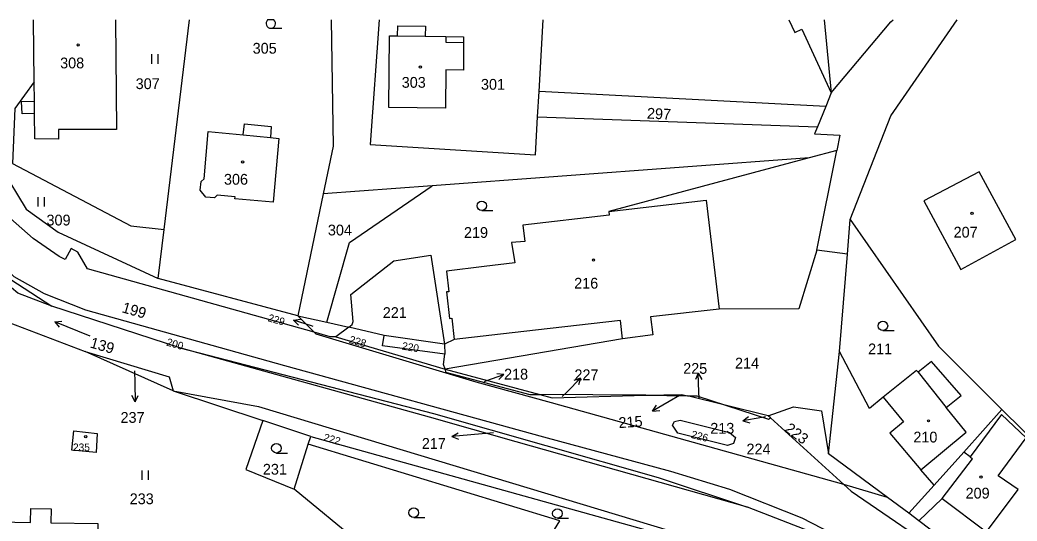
# Model space of a CAD drawing. Extents: x -520431 to -517205, y -1075927 to -1074013.
# Drawn here: x -518035.5 to -517878.1, y -1074093.8 to -1074014.8 of the extents above; entities that cross this region are included whole.
import ezdxf

# ---------------------------------------------------------------- set-up
doc = ezdxf.new("R2010")
doc.units = 0
for name, color, linetype in [('Hranice parcel', 7, 'Continuous'), ('Parcelní čísla', 7, 'Continuous'), ('Pop  PČ popisy', 7, 'Continuous'), ('Vnitřní kresba', 7, 'Continuous'), ('Značky budov', 7, 'Continuous'), ('Značky kultur', 7, 'Continuous')]:
    doc.layers.add(name, color=color, linetype=linetype)

msp = doc.modelspace()

# ---------------------------------------------------------------- linework, layer by layer
at = {"layer": 'Hranice parcel'}
for p, q in [((-518033.22, -1074024.56), (-518033.34, -1074014.78)), ((-518012.72, -1074047.85), (-518008.75, -1074014.78)), ((-517986.35, -1074014.78), (-517986.05, -1074034.68)), ((-518033.18, -1074027.62), (-518033.22, -1074024.56)), ((-517953.81, -1074030.04), (-517953.57, -1074026.08)), ((-517908.34, -1074028.41), (-517953.57, -1074026.08)), ((-517907.48, -1074026.26), (-517908.34, -1074028.41)), ((-517908.34, -1074028.41), (-517909.63, -1074031.62)), ((-517953.81, -1074030.04), (-517909.63, -1074031.62)), ((-517986.05, -1074034.68), (-517987.62, -1074042.23)), ((-517906.59, -1074035.35), (-517910.97, -1074036.55)), ((-517909.74, -1074051.08), (-517906.59, -1074035.35)), ((-517910.97, -1074036.55), (-517970.43, -1074040.96)), ((-517910.97, -1074036.55), (-517942.57, -1074044.98)), ((-517970.43, -1074040.96), (-517987.62, -1074042.23)), ((-517987.62, -1074042.23), (-517991.61, -1074061.46)), ((-517904.92, -1074051.73), (-517904.47, -1074046.28)), ((-518013.65, -1074055.54), (-518012.72, -1074047.85)), ((-517904.92, -1074051.73), (-517909.74, -1074051.08)), ((-517906.18, -1074067.07), (-517904.92, -1074051.73)), ((-517989.05, -1074064.04), (-518024.8, -1074054.02)), ((-517991.61, -1074061.46), (-518013.65, -1074055.54)), ((-518010.25, -1074066.51), (-518030.46, -1074059.93)), ((-517991.61, -1074061.46), (-517987.05, -1074062.45)), ((-517991.61, -1074061.46), (-517989.05, -1074064.04)), ((-517987.05, -1074062.45), (-517983.59, -1074063.23)), ((-517983.59, -1074063.23), (-517985.63, -1074064.79)), ((-517983.59, -1074063.23), (-517983.04, -1074062.81)), ((-517978.03, -1074064.56), (-517983.59, -1074063.23)), ((-517986.51, -1074064.75), (-517989.05, -1074064.04)), ((-517985.63, -1074064.79), (-517986.51, -1074064.75)), ((-517985.63, -1074064.79), (-517968.41, -1074069.88)), ((-517968.48, -1074065.94), (-517978.03, -1074064.56)), ((-517968.48, -1074065.94), (-517968.46, -1074067.51)), ((-518011.3, -1074073.28), (-518025.19, -1074067.07)), ((-517907.92, -1074083.21), (-517906.18, -1074067.07)), ((-517968.41, -1074069.88), (-517953.47, -1074073.86)), ((-518011.3, -1074073.28), (-517997.17, -1074077.96)), ((-517936.72, -1074073.99), (-517953.47, -1074073.86)), ((-517936.72, -1074073.99), (-517930.13, -1074074.06)), ((-517924, -1074075.59), (-517930.13, -1074074.06)), ((-517917.42, -1074077.23), (-517924, -1074075.59)), ((-517886.57, -1074082.94), (-517880.56, -1074076.24)), ((-517917.07, -1074077.55), (-517917.42, -1074077.23)), ((-517917.07, -1074077.55), (-517905.48, -1074088.05)), ((-517989.6, -1074080.49), (-517997.17, -1074077.96)), ((-517989.98, -1074081.71), (-517989.6, -1074080.49)), ((-517989.6, -1074080.49), (-517922.6, -1074099.11)), ((-517992.22, -1074088.81), (-517989.98, -1074081.71)), ((-517950.31, -1074093.77), (-517989.98, -1074081.71)), ((-517898.6, -1074090.11), (-517907.92, -1074083.21)), ((-517886.57, -1074082.94), (-517891.25, -1074088.16)), ((-517979.58, -1074099.18), (-517992.22, -1074088.81)), ((-517905.48, -1074088.05), (-517904.3, -1074089.11)), ((-517898.6, -1074090.11), (-517905.48, -1074088.05)), ((-517891.25, -1074088.16), (-517895.23, -1074092.6)), ((-517895.23, -1074092.6), (-517898.6, -1074090.11)), ((-517910.79, -1074095.45), (-517920.67, -1074091.64)), ((-517893.63, -1074093.8), (-517895.23, -1074092.6)), ((-517951.12, -1074095.17), (-517950.31, -1074093.77)), ((-517876.3, -1074106.78), (-517893.63, -1074093.8))]:
    msp.add_line(p, q, dxfattribs=at)
for points in [[(-518024.8, -1074054.02), (-518026.36, -1074051.41), (-518027.39, -1074050.82), (-518028.34, -1074052.56), (-518029.28, -1074052.1), (-518033.39, -1074049.28), (-518037.85, -1074045.29), (-518043.66, -1074037.25), (-518046.28, -1074031.8), (-518047.85, -1074028.08), (-518052.23, -1074014.78)], [(-518020.41, -1074014.78), (-518020.23, -1074032.08), (-518029.38, -1074032.08), (-518029.4, -1074033.57), (-518033.11, -1074033.51), (-518033.16, -1074029.55), (-518033.18, -1074027.62)], [(-517978.79, -1074014.78), (-517980.22, -1074034.43), (-517954.14, -1074036.05), (-517953.81, -1074030.04)], [(-517953.57, -1074026.08), (-517952.94, -1074014.78)], [(-517914.16, -1074014.78), (-517913.19, -1074016.76), (-517912.09, -1074016.23), (-517907.48, -1074026.26)], [(-517908.57, -1074014.78), (-517907.48, -1074026.26)], [(-517907.48, -1074026.26), (-517898.04, -1074015.08), (-517897.72, -1074014.78)], [(-517904.47, -1074046.28), (-517898.07, -1074029.91), (-517887.61, -1074014.78)], [(-517977.16, -1074017.31), (-517975.91, -1074017.31), (-517975.87, -1074015.7), (-517971.51, -1074015.76), (-517971.53, -1074017.36), (-517968.26, -1074017.4), (-517965.47, -1074017.43), (-517965.47, -1074018.32), (-517965.49, -1074022.71), (-517968.3, -1074022.66), (-517968.35, -1074028.69), (-517977.26, -1074028.59), (-517977.16, -1074017.31)], [(-518033.22, -1074024.56), (-518036.28, -1074028.73), (-518036.65, -1074037.44), (-518017.96, -1074047.27), (-518012.72, -1074047.85)], [(-518054.93, -1074030.17), (-518051.62, -1074037.84), (-518048.22, -1074043.62), (-518043.98, -1074048.85), (-518040.3, -1074053.57), (-518030.46, -1074059.93)], [(-517889.1, -1074107.75), (-517905.75, -1074096.63), (-517912.05, -1074093.34), (-517923.48, -1074088.82), (-517932.79, -1074086.03), (-517952.8, -1074080.58), (-517993.67, -1074069.35), (-518025.1, -1074060.56), (-518031.6, -1074057.97), (-518036.37, -1074055.31), (-518043.81, -1074047.94), (-518049.25, -1074040.16), (-518052.28, -1074033.84), (-518053.74, -1074030.31)], [(-518041.25, -1074031.07), (-518038.45, -1074038.13), (-518034.49, -1074044.61), (-518029.45, -1074048.27), (-518013.65, -1074055.54)], [(-517909.63, -1074031.62), (-517910.1, -1074032.76), (-517906.09, -1074032.97), (-517906.59, -1074035.35)], [(-517995.53, -1074043.55), (-518001.57, -1074043), (-518001.54, -1074042.7), (-518004.36, -1074042.44), (-518004.79, -1074042.86), (-518006.17, -1074042.71), (-518007.06, -1074041.61), (-518006.86, -1074040.26), (-518006.42, -1074039.86), (-518005.78, -1074032.39), (-518000.24, -1074032.93), (-517995.93, -1074033.34), (-517994.61, -1074033.47), (-517995.53, -1074043.55)], [(-517878.33, -1074049.43), (-517884.11, -1074038.72), (-517892.84, -1074043.33), (-517887.01, -1074054.12), (-517878.33, -1074049.43)], [(-517987.05, -1074062.45), (-517983.47, -1074049.87), (-517970.43, -1074040.96)], [(-517942.57, -1074044.98), (-517942.53, -1074045.6), (-517956.14, -1074047.14), (-517955.82, -1074049.75), (-517957.91, -1074049.89), (-517957.4, -1074053.11), (-517962.23, -1074053.68), (-517968.18, -1074054.39), (-517967.82, -1074057.65), (-517968.19, -1074057.69), (-517967.71, -1074061.86), (-517967.35, -1074061.82), (-517966.98, -1074065.17), (-517968.48, -1074065.94)], [(-517904.47, -1074046.28), (-517890.53, -1074066.25), (-517880.56, -1074076.24)], [(-517909.74, -1074051.08), (-517912.6, -1074060.35), (-517925.13, -1074060.39)], [(-517983.04, -1074062.81), (-517982.9, -1074062.37), (-517983.27, -1074058.09), (-517976.47, -1074052.79), (-517970.63, -1074051.9), (-517968.48, -1074065.94)], [(-518030.46, -1074059.93), (-518035.83, -1074057.88), (-518037.82, -1074056.21)], [(-517925.13, -1074060.39), (-517935.97, -1074061.63), (-517935.64, -1074064.47), (-517940.43, -1074065.08), (-517968.41, -1074069.88)], [(-518040.72, -1074060.96), (-518038.45, -1074062.02), (-518025.19, -1074067.07)], [(-517905.48, -1074088.05), (-517951.62, -1074075.17), (-517963.5, -1074071.92), (-517988.72, -1074064.36), (-517989.05, -1074064.04)], [(-517968.46, -1074067.51), (-517978.25, -1074066.19), (-517978.03, -1074064.56)], [(-518010.25, -1074066.51), (-517970.23, -1074076.85), (-517934.78, -1074086.97), (-517920.67, -1074091.64)], [(-517920.67, -1074091.64), (-517957.17, -1074081.3), (-517970.84, -1074077.42), (-518010.25, -1074066.51)], [(-518025.19, -1074067.07), (-518011.95, -1074071.05), (-518011.3, -1074073.28)], [(-517968.41, -1074069.88), (-517968.67, -1074069.15), (-517968.46, -1074067.51)], [(-517891.25, -1074088.16), (-517893.31, -1074085.75), (-517886.18, -1074079.8), (-517889.32, -1074075.89), (-517886.99, -1074074.01), (-517891.63, -1074068.63), (-517893.77, -1074070.35), (-517894, -1074070.06), (-517899.28, -1074074.29), (-517901.42, -1074076.08), (-517906.18, -1074067.07)], [(-517968.41, -1074069.88), (-517968.32, -1074070.34), (-517955.01, -1074073.85), (-517953.47, -1074073.86)], [(-518011.3, -1074073.28), (-517997.83, -1074075.77), (-517929.9, -1074096.27), (-517922.6, -1074099.11)], [(-517953.47, -1074073.86), (-517951.48, -1074074.39), (-517936.72, -1074073.99)], [(-517936.72, -1074073.99), (-517931.03, -1074073.84), (-517930.13, -1074074.06)], [(-517930.13, -1074074.06), (-517928.69, -1074074.05), (-517924, -1074075.59)], [(-517924, -1074075.59), (-517917.36, -1074077.76), (-517917.07, -1074077.55)], [(-517917.42, -1074077.23), (-517913.43, -1074075.79), (-517909.02, -1074076.42), (-517907.92, -1074083.21)], [(-517880.56, -1074076.24), (-517870.64, -1074085.96), (-517865.01, -1074089.97)], [(-517893.63, -1074093.8), (-517889.99, -1074090.26), (-517882.99, -1074095.54), (-517877.96, -1074088.82), (-517881.12, -1074086.71), (-517876.71, -1074080.7), (-517880.59, -1074077.04), (-517885.57, -1074083.7), (-517886.57, -1074082.94)], [(-517997.17, -1074077.96), (-517999.84, -1074085.67), (-517992.22, -1074088.81)], [(-517931.67, -1074079.95), (-517932.5, -1074078.72), (-517932.21, -1074078.1), (-517931.31, -1074077.9), (-517923.5, -1074079.84), (-517922.6, -1074080.66), (-517922.87, -1074081.61), (-517923.86, -1074081.91), (-517931.67, -1074079.95)], [(-518027.3, -1074082.62), (-518026.98, -1074079.59), (-518023.28, -1074080.02), (-518023.47, -1074083.03), (-518027.3, -1074082.62)], [(-517904.3, -1074089.11), (-517888.48, -1074099.95), (-517882.39, -1074105.24), (-517863.87, -1074122.33), (-517832.77, -1074151.27), (-517816.67, -1074166.61)], [(-518023.42, -1074105.69), (-518041.47, -1074105.37), (-518041.29, -1074093.91), (-518033.81, -1074094.04), (-518033.76, -1074091.82), (-518030.57, -1074091.9), (-518030.6, -1074094.09), (-518023.21, -1074094.2), (-518023.4, -1074102.57)]]:
    msp.add_lwpolyline(points, dxfattribs=at)
at = {"layer": 'Pop  PČ popisy'}
for p, q in [((-517992.32, -1074062.12), (-517991.22, -1074061.96)), ((-517989.47, -1074063.05), (-517992.32, -1074062.12)), ((-517992.32, -1074062.12), (-517991.53, -1074062.91)), ((-517989.19, -1074063.14), (-517989.47, -1074063.05)), ((-518017.39, -1074070.11), (-518017.35, -1074072.03)), ((-517961.95, -1074071.73), (-517959.13, -1074070.7)), ((-517959.13, -1074070.7), (-517960.24, -1074070.58)), ((-517959.13, -1074070.7), (-517959.9, -1074071.52)), ((-517949.14, -1074073.42), (-517947.02, -1074071.3)), ((-517947.02, -1074071.3), (-517948.08, -1074071.65)), ((-517947.02, -1074071.3), (-517947.37, -1074072.36)), ((-517928.45, -1074070.49), (-517928.91, -1074071.51)), ((-517928.34, -1074073.49), (-517928.45, -1074070.49)), ((-517928.45, -1074070.49), (-517927.91, -1074071.47)), ((-518017.35, -1074072.03), (-518017.3, -1074075.03)), ((-517962.16, -1074071.81), (-517961.95, -1074071.73)), ((-518017.3, -1074075.03), (-518017.82, -1074074.04)), ((-518017.3, -1074075.03), (-518016.81, -1074074.02)), ((-517949.9, -1074074.19), (-517949.14, -1074073.42)), ((-517931.41, -1074074), (-517933.05, -1074074.97)), ((-517928.31, -1074074.4), (-517928.34, -1074073.49)), ((-517933.05, -1074074.97), (-517935.65, -1074076.47)), ((-517935.65, -1074076.47), (-517935.03, -1074075.54)), ((-517935.65, -1074076.47), (-517934.53, -1074076.4)), ((-517921.4, -1074078.02), (-517920.5, -1074077.35)), ((-517918.44, -1074077.5), (-517921.4, -1074078.02)), ((-517917.86, -1074077.4), (-517918.44, -1074077.5)), ((-517921.4, -1074078.02), (-517920.32, -1074078.34)), ((-517967.31, -1074080.49), (-517966.36, -1074079.91)), ((-517964.32, -1074080.23), (-517967.31, -1074080.49)), ((-517967.31, -1074080.49), (-517966.27, -1074080.9)), ((-517960.75, -1074079.91), (-517964.32, -1074080.23))]:
    msp.add_line(p, q, dxfattribs=at)
at = {"layer": 'Vnitřní kresba'}
for p, q in [((-517975.91, -1074017.31), (-517971.53, -1074017.36)), ((-517968.26, -1074017.4), (-517968.26, -1074018.29)), ((-517968.26, -1074018.29), (-517965.47, -1074018.32)), ((-518035.25, -1074027.65), (-518033.18, -1074027.62)), ((-518035.14, -1074029.57), (-518035.25, -1074027.65)), ((-518033.16, -1074029.55), (-518035.14, -1074029.57)), ((-518000.24, -1074032.93), (-518000.07, -1074031.15)), ((-518000.07, -1074031.15), (-517995.82, -1074031.61)), ((-517995.82, -1074031.61), (-517995.93, -1074033.34)), ((-517942.57, -1074044.98), (-517927.2, -1074043.19)), ((-517927.2, -1074043.19), (-517925.13, -1074060.39)), ((-517954.11, -1074063.7), (-517961.04, -1074064.49)), ((-517940.73, -1074062.17), (-517954.11, -1074063.7)), ((-517940.43, -1074065.08), (-517940.73, -1074062.17)), ((-517961.04, -1074064.49), (-517966.98, -1074065.17)), ((-517893.77, -1074070.35), (-517889.32, -1074075.89)), ((-517899.28, -1074074.29), (-517896.09, -1074078.16)), ((-517896.09, -1074078.16), (-517898.24, -1074079.97)), ((-517898.24, -1074079.97), (-517893.31, -1074085.75)), ((-517889.99, -1074090.26), (-517885.18, -1074083.99)), ((-517885.57, -1074083.7), (-517885.18, -1074083.99))]:
    msp.add_line(p, q, dxfattribs=at)
at = {"layer": 'Značky budov'}
for centre in [(-518026.29, -1074018.73), (-517972.29, -1074022.21), (-518000.35, -1074037.18), (-517885.25, -1074045.29), (-517944.98, -1074052.65), (-517892.12, -1074078.01), (-518025.1, -1074080.5), (-517883.84, -1074086.88)]:
    msp.add_circle(centre, 0.175, dxfattribs=at)
at = {"layer": 'Značky kultur'}
for p, q in [((-517995.4, -1074014.78), (-517996.41, -1074014.78)), ((-517995.9, -1074016.09), (-517994.15, -1074016.09)), ((-518014.66, -1074021.68), (-518014.66, -1074020.18)), ((-518013.66, -1074021.68), (-518013.66, -1074020.18)), ((-518032.61, -1074044.22), (-518032.61, -1074042.72)), ((-518031.61, -1074044.22), (-518031.61, -1074042.72)), ((-517962.61, -1074044.85), (-517960.86, -1074044.85)), ((-518029.98, -1074062.4), (-518028.89, -1074062.3)), ((-518024.42, -1074064.65), (-518029.98, -1074062.4)), ((-518029.98, -1074062.4), (-518029.27, -1074063.23)), ((-517899.31, -1074063.79), (-517897.56, -1074063.79)), ((-517995.02, -1074083.09), (-517993.27, -1074083.09)), ((-518016.21, -1074087.34), (-518016.21, -1074085.84)), ((-518015.21, -1074087.34), (-518015.21, -1074085.84)), ((-517973.35, -1074093.25), (-517971.6, -1074093.25)), ((-517950.68, -1074093.38), (-517948.93, -1074093.38))]:
    msp.add_line(p, q, dxfattribs=at)
for centre in [(-517962.61, -1074044.1), (-517899.31, -1074063.04), (-517995.02, -1074082.34), (-517973.35, -1074092.5), (-517950.68, -1074092.63)]:
    msp.add_circle(centre, 0.75, dxfattribs=at)
msp.add_arc((-517995.9, -1074015.34), 0.75, 132.2802, 47.7198, dxfattribs=at)

# ---------------------------------------------------------------- texts
at = {"layer": 'Parcelní čísla'}
for s, height, p in [('305', 1.7, (-517998.76, -1074020.1)), ('308', 1.7, (-518029.14, -1074022.42)), ('307', 1.7, (-518017.22, -1074025.69)), ('303', 1.7, (-517975.24, -1074025.48)), ('301', 1.7, (-517962.74, -1074025.79)), ('306', 1.7, (-518003.29, -1074040.77)), ('309', 1.7, (-518031.29, -1074047.2)), ('304', 1.7, (-517986.89, -1074048.77)), ('219', 1.7, (-517965.42, -1074049.16)), ('207', 1.7, (-517888.16, -1074049.11)), ('216', 1.7, (-517948.03, -1074057.16)), ('221', 1.7, (-517978.23, -1074061.79)), ('211', 1.7, (-517901.65, -1074067.52)), ('214', 1.7, (-517922.65, -1074069.76)), ('218', 1.7, (-517959.09, -1074071.5)), ('227', 1.7, (-517947.99, -1074071.6)), ('225', 1.7, (-517930.83, -1074070.6)), ('237', 1.7, (-518019.61, -1074078.33)), ('213', 1.7, (-517926.56, -1074080.04)), ('217', 1.7, (-517972.07, -1074082.43)), ('210', 1.7, (-517894.51, -1074081.43)), ('235', 1.2, (-518027.12, -1074082.79)), ('224', 1.7, (-517920.84, -1074083.31)), ('231', 1.7, (-517997.15, -1074086.5)), ('209', 1.7, (-517886.27, -1074090.27)), ('233', 1.7, (-518018.16, -1074091.16))]:
    msp.add_text(s, height=height, dxfattribs=at).set_placement(p)
for s, height, rotation, p in [('297', 1.7, 357, (-517936.58, -1074030.33)), ('199', 1.7, 344, (-518019.5, -1074060.87)), ('229', 1.19, 344, (-517996.44, -1074062.28)), ('139', 1.7, 344, (-518024.54, -1074066.42)), ('200', 1.2, 344, (-518012.46, -1074066.11)), ('228', 1.2, 344, (-517983.62, -1074065.71)), ('220', 1.2, 350, (-517975.28, -1074066.75)), ('215', 1.7, 4, (-517940.97, -1074079.17)), ('223', 1.7, 323, (-517914.93, -1074079.54)), ('222', 1.2, 344, (-517987.68, -1074081.13)), ('226', 1.2, 346, (-517929.66, -1074080.69))]:
    msp.add_text(s, height=height, rotation=rotation, dxfattribs=at).set_placement(p)

doc.saveas('drawing.dxf')
